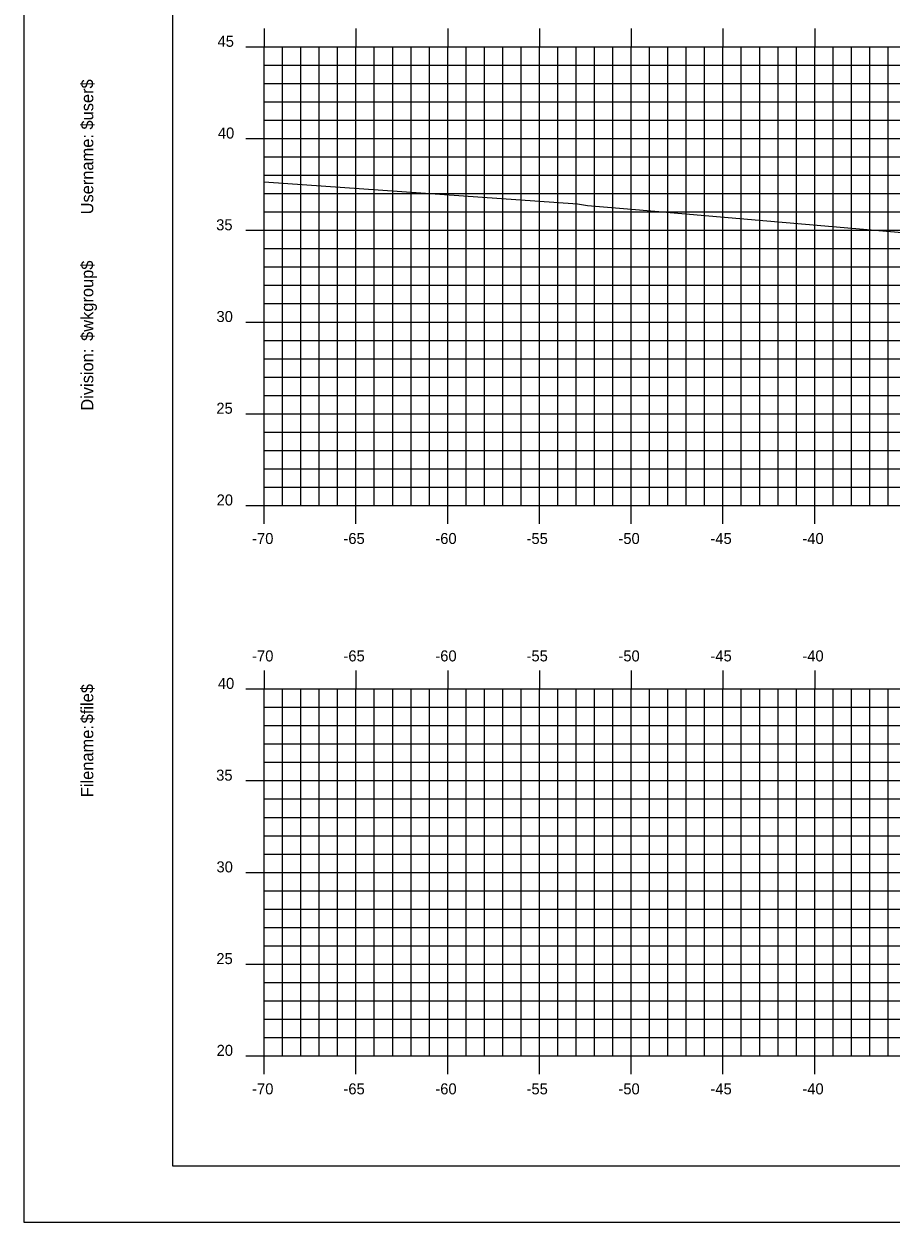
# Model space of a CAD drawing. Extents: x 1026131 to 1026301, y 394697 to 394807.
# Drawn here: x 1026131.3 to 1026178.5, y 394696.5 to 394761.9 of the extents above; entities that cross this region are included whole.
import ezdxf

# ---------------------------------------------------------------- set-up
doc = ezdxf.new("R2010")
doc.units = 0
for name, color, linetype in [('BORDER', 7, 'Continuous'), ('H_V ANNOTATION', 7, 'Continuous'), ('MAJOR', 7, 'Continuous'), ('MINOR', 7, 'Continuous'), ('PLOT BOUNDARY', 7, 'Continuous'), ('S_Roadway_Centerline', 7, 'Continuous')]:
    doc.layers.add(name, color=color, linetype=linetype)

msp = doc.modelspace()

# ---------------------------------------------------------------- linework, layer by layer
at = {"layer": 'BORDER'}
for p, q in [((1026139.345, 394804.607), (1026139.345, 394699.607)), ((1026139.345, 394699.607), (1026299.345, 394699.607))]:
    msp.add_line(p, q, dxfattribs=at)
at = {"layer": 'MAJOR'}
for p, q in [((1026144.344, 394761.609), (1026144.344, 394760.607)), ((1026149.344, 394761.609), (1026149.344, 394760.607)), ((1026154.344, 394761.609), (1026154.344, 394760.607)), ((1026159.344, 394761.609), (1026159.344, 394760.607)), ((1026164.344, 394761.609), (1026164.344, 394760.607)), ((1026169.344, 394761.609), (1026169.344, 394760.607)), ((1026174.344, 394761.609), (1026174.344, 394760.607)), ((1026143.342, 394760.607), (1026144.344, 394760.607)), ((1026144.344, 394760.607), (1026284.344, 394760.607)), ((1026144.344, 394735.607), (1026144.344, 394760.607)), ((1026149.344, 394735.607), (1026149.344, 394760.607)), ((1026154.344, 394735.607), (1026154.344, 394760.607)), ((1026159.344, 394735.607), (1026159.344, 394760.607)), ((1026164.344, 394735.607), (1026164.344, 394760.607)), ((1026169.344, 394735.607), (1026169.344, 394760.607)), ((1026174.344, 394735.607), (1026174.344, 394760.607)), ((1026143.342, 394755.607), (1026144.344, 394755.607)), ((1026144.344, 394755.607), (1026284.344, 394755.607)), ((1026143.342, 394750.607), (1026144.344, 394750.607)), ((1026144.344, 394750.607), (1026284.344, 394750.607)), ((1026143.342, 394745.607), (1026144.344, 394745.607)), ((1026144.344, 394745.607), (1026284.344, 394745.607)), ((1026143.342, 394740.607), (1026144.344, 394740.607)), ((1026144.344, 394740.607), (1026284.344, 394740.607)), ((1026143.342, 394735.607), (1026144.344, 394735.607)), ((1026144.344, 394735.607), (1026284.344, 394735.607)), ((1026144.344, 394734.605), (1026144.344, 394735.607)), ((1026149.344, 394734.605), (1026149.344, 394735.607)), ((1026154.344, 394734.605), (1026154.344, 394735.607)), ((1026159.344, 394734.605), (1026159.344, 394735.607)), ((1026164.344, 394734.605), (1026164.344, 394735.607)), ((1026169.344, 394734.605), (1026169.344, 394735.607)), ((1026174.344, 394734.605), (1026174.344, 394735.607)), ((1026144.344, 394726.609), (1026144.344, 394725.607)), ((1026149.344, 394726.609), (1026149.344, 394725.607)), ((1026154.344, 394726.609), (1026154.344, 394725.607)), ((1026159.344, 394726.609), (1026159.344, 394725.607)), ((1026164.344, 394726.609), (1026164.344, 394725.607)), ((1026169.344, 394726.609), (1026169.344, 394725.607)), ((1026174.344, 394726.609), (1026174.344, 394725.607)), ((1026143.342, 394725.607), (1026144.344, 394725.607)), ((1026144.344, 394725.607), (1026284.344, 394725.607)), ((1026144.344, 394705.607), (1026144.344, 394725.607)), ((1026149.344, 394705.607), (1026149.344, 394725.607)), ((1026154.344, 394705.607), (1026154.344, 394725.607)), ((1026159.344, 394705.607), (1026159.344, 394725.607)), ((1026164.344, 394705.607), (1026164.344, 394725.607)), ((1026169.344, 394705.607), (1026169.344, 394725.607)), ((1026174.344, 394705.607), (1026174.344, 394725.607)), ((1026143.342, 394720.607), (1026144.344, 394720.607)), ((1026144.344, 394720.607), (1026284.344, 394720.607)), ((1026143.342, 394715.607), (1026144.344, 394715.607)), ((1026144.344, 394715.607), (1026284.344, 394715.607)), ((1026143.342, 394710.607), (1026144.344, 394710.607)), ((1026144.344, 394710.607), (1026284.344, 394710.607)), ((1026143.342, 394705.607), (1026144.344, 394705.607)), ((1026144.344, 394705.607), (1026284.344, 394705.607)), ((1026144.344, 394704.605), (1026144.344, 394705.607)), ((1026149.344, 394704.605), (1026149.344, 394705.607)), ((1026154.344, 394704.605), (1026154.344, 394705.607)), ((1026159.344, 394704.605), (1026159.344, 394705.607)), ((1026164.344, 394704.605), (1026164.344, 394705.607)), ((1026169.344, 394704.605), (1026169.344, 394705.607)), ((1026174.344, 394704.605), (1026174.344, 394705.607))]:
    msp.add_line(p, q, dxfattribs=at)
at = {"layer": 'MINOR'}
for p, q in [((1026145.344, 394735.607), (1026145.344, 394760.607)), ((1026146.344, 394735.607), (1026146.344, 394760.607)), ((1026147.344, 394735.607), (1026147.344, 394760.607)), ((1026148.344, 394735.607), (1026148.344, 394760.607)), ((1026150.344, 394735.607), (1026150.344, 394760.607)), ((1026151.344, 394735.607), (1026151.344, 394760.607)), ((1026152.344, 394735.607), (1026152.344, 394760.607)), ((1026153.344, 394735.607), (1026153.344, 394760.607)), ((1026155.344, 394735.607), (1026155.344, 394760.607)), ((1026156.344, 394735.607), (1026156.344, 394760.607)), ((1026157.344, 394735.607), (1026157.344, 394760.607)), ((1026158.344, 394735.607), (1026158.344, 394760.607)), ((1026160.344, 394735.607), (1026160.344, 394760.607)), ((1026161.344, 394735.607), (1026161.344, 394760.607)), ((1026162.344, 394735.607), (1026162.344, 394760.607)), ((1026163.344, 394735.607), (1026163.344, 394760.607)), ((1026165.344, 394735.607), (1026165.344, 394760.607)), ((1026166.344, 394735.607), (1026166.344, 394760.607)), ((1026167.344, 394735.607), (1026167.344, 394760.607)), ((1026168.344, 394735.607), (1026168.344, 394760.607)), ((1026170.344, 394735.607), (1026170.344, 394760.607)), ((1026171.344, 394735.607), (1026171.344, 394760.607)), ((1026172.344, 394735.607), (1026172.344, 394760.607)), ((1026173.344, 394735.607), (1026173.344, 394760.607)), ((1026175.344, 394735.607), (1026175.344, 394760.607)), ((1026176.344, 394735.607), (1026176.344, 394760.607)), ((1026177.344, 394735.607), (1026177.344, 394760.607)), ((1026178.344, 394735.607), (1026178.344, 394760.607)), ((1026144.344, 394759.607), (1026284.344, 394759.607)), ((1026144.344, 394759.607), (1026145.346, 394759.607)), ((1026144.344, 394758.607), (1026284.344, 394758.607)), ((1026144.344, 394758.607), (1026145.346, 394758.607)), ((1026144.344, 394757.607), (1026284.344, 394757.607)), ((1026144.344, 394757.607), (1026145.346, 394757.607)), ((1026144.344, 394756.607), (1026284.344, 394756.607)), ((1026144.344, 394756.607), (1026145.346, 394756.607)), ((1026144.344, 394754.607), (1026284.344, 394754.607)), ((1026144.344, 394754.607), (1026145.346, 394754.607)), ((1026144.344, 394753.607), (1026284.344, 394753.607)), ((1026144.344, 394753.607), (1026145.346, 394753.607)), ((1026144.344, 394752.607), (1026284.344, 394752.607)), ((1026144.344, 394752.607), (1026145.346, 394752.607)), ((1026144.344, 394751.607), (1026284.344, 394751.607)), ((1026144.344, 394751.607), (1026145.346, 394751.607)), ((1026144.344, 394749.607), (1026284.344, 394749.607)), ((1026144.344, 394749.607), (1026145.346, 394749.607)), ((1026144.344, 394748.607), (1026284.344, 394748.607)), ((1026144.344, 394748.607), (1026145.346, 394748.607)), ((1026144.344, 394747.607), (1026284.344, 394747.607)), ((1026144.344, 394747.607), (1026145.346, 394747.607)), ((1026144.344, 394746.607), (1026284.344, 394746.607)), ((1026144.344, 394746.607), (1026145.346, 394746.607)), ((1026144.344, 394744.607), (1026284.344, 394744.607)), ((1026144.344, 394744.607), (1026145.346, 394744.607)), ((1026144.344, 394743.607), (1026284.344, 394743.607)), ((1026144.344, 394743.607), (1026145.346, 394743.607)), ((1026144.344, 394742.607), (1026284.344, 394742.607)), ((1026144.344, 394742.607), (1026145.346, 394742.607)), ((1026144.344, 394741.607), (1026284.344, 394741.607)), ((1026144.344, 394741.607), (1026145.346, 394741.607)), ((1026144.344, 394739.607), (1026284.344, 394739.607)), ((1026144.344, 394739.607), (1026145.346, 394739.607)), ((1026144.344, 394738.607), (1026284.344, 394738.607)), ((1026144.344, 394738.607), (1026145.346, 394738.607)), ((1026144.344, 394737.607), (1026284.344, 394737.607)), ((1026144.344, 394737.607), (1026145.346, 394737.607)), ((1026144.344, 394736.607), (1026284.344, 394736.607)), ((1026144.344, 394736.607), (1026145.346, 394736.607)), ((1026145.344, 394705.607), (1026145.344, 394725.607)), ((1026146.344, 394705.607), (1026146.344, 394725.607)), ((1026147.344, 394705.607), (1026147.344, 394725.607)), ((1026148.344, 394705.607), (1026148.344, 394725.607)), ((1026150.344, 394705.607), (1026150.344, 394725.607)), ((1026151.344, 394705.607), (1026151.344, 394725.607)), ((1026152.344, 394705.607), (1026152.344, 394725.607)), ((1026153.344, 394705.607), (1026153.344, 394725.607)), ((1026155.344, 394705.607), (1026155.344, 394725.607)), ((1026156.344, 394705.607), (1026156.344, 394725.607)), ((1026157.344, 394705.607), (1026157.344, 394725.607)), ((1026158.344, 394705.607), (1026158.344, 394725.607)), ((1026160.344, 394705.607), (1026160.344, 394725.607)), ((1026161.344, 394705.607), (1026161.344, 394725.607)), ((1026162.344, 394705.607), (1026162.344, 394725.607)), ((1026163.344, 394705.607), (1026163.344, 394725.607)), ((1026165.344, 394705.607), (1026165.344, 394725.607)), ((1026166.344, 394705.607), (1026166.344, 394725.607)), ((1026167.344, 394705.607), (1026167.344, 394725.607)), ((1026168.344, 394705.607), (1026168.344, 394725.607)), ((1026170.344, 394705.607), (1026170.344, 394725.607)), ((1026171.344, 394705.607), (1026171.344, 394725.607)), ((1026172.344, 394705.607), (1026172.344, 394725.607)), ((1026173.344, 394705.607), (1026173.344, 394725.607)), ((1026175.344, 394705.607), (1026175.344, 394725.607)), ((1026176.344, 394705.607), (1026176.344, 394725.607)), ((1026177.344, 394705.607), (1026177.344, 394725.607)), ((1026178.344, 394705.607), (1026178.344, 394725.607)), ((1026144.344, 394724.607), (1026284.344, 394724.607)), ((1026144.344, 394724.607), (1026145.346, 394724.607)), ((1026144.344, 394723.607), (1026284.344, 394723.607)), ((1026144.344, 394723.607), (1026145.346, 394723.607)), ((1026144.344, 394722.607), (1026284.344, 394722.607)), ((1026144.344, 394722.607), (1026145.346, 394722.607)), ((1026144.344, 394721.607), (1026284.344, 394721.607)), ((1026144.344, 394721.607), (1026145.346, 394721.607)), ((1026144.344, 394719.607), (1026284.344, 394719.607)), ((1026144.344, 394719.607), (1026145.346, 394719.607)), ((1026144.344, 394718.607), (1026284.344, 394718.607)), ((1026144.344, 394718.607), (1026145.346, 394718.607)), ((1026144.344, 394717.607), (1026284.344, 394717.607)), ((1026144.344, 394717.607), (1026145.346, 394717.607)), ((1026144.344, 394716.607), (1026284.344, 394716.607)), ((1026144.344, 394716.607), (1026145.346, 394716.607)), ((1026144.344, 394714.607), (1026284.344, 394714.607)), ((1026144.344, 394714.607), (1026145.346, 394714.607)), ((1026144.344, 394713.607), (1026284.344, 394713.607)), ((1026144.344, 394713.607), (1026145.346, 394713.607)), ((1026144.344, 394712.607), (1026284.344, 394712.607)), ((1026144.344, 394712.607), (1026145.346, 394712.607)), ((1026144.344, 394711.607), (1026284.344, 394711.607)), ((1026144.344, 394711.607), (1026145.346, 394711.607)), ((1026144.344, 394709.607), (1026284.344, 394709.607)), ((1026144.344, 394709.607), (1026145.346, 394709.607)), ((1026144.344, 394708.607), (1026284.344, 394708.607)), ((1026144.344, 394708.607), (1026145.346, 394708.607)), ((1026144.344, 394707.607), (1026284.344, 394707.607)), ((1026144.344, 394707.607), (1026145.346, 394707.607)), ((1026144.344, 394706.607), (1026284.344, 394706.607)), ((1026144.344, 394706.607), (1026145.346, 394706.607))]:
    msp.add_line(p, q, dxfattribs=at)
at = {"layer": 'PLOT BOUNDARY'}
msp.add_lwpolyline([(1026131.251, 394696.548), (1026301.251, 394696.548), (1026301.251, 394806.548), (1026131.251, 394806.548)], close=True, dxfattribs=at)
at = {"layer": 'S_Roadway_Centerline'}
msp.add_lwpolyline([(1026144.344, 394753.246), (1026161.416, 394752.044), (1026161.957, 394751.958), (1026164.577, 394751.744), (1026181.002, 394750.326)], dxfattribs=at)

# ---------------------------------------------------------------- texts
at = {"layer": 'BORDER'}
for s, p in [('$user$', (1026135.029, 394756.098)), ('Username:', (1026135.029, 394751.474)), ('$wkgroup$', (1026135.029, 394744.576)), ('Division:', (1026135.029, 394740.773)), ('$file$', (1026135.029, 394723.732)), ('Filename:', (1026135.029, 394719.705))]:
    msp.add_text(s, height=0.6696, rotation=90, dxfattribs=at).set_placement(p)
at = {"layer": 'H_V ANNOTATION'}
for s, p in [('45', (1026141.801, 394760.607)), ('40', (1026141.817, 394755.607)), ('35', (1026141.726, 394750.607)), ('30', (1026141.742, 394745.607)), ('25', (1026141.736, 394740.607)), ('20', (1026141.752, 394735.607)), ('-70', (1026143.686, 394733.507)), ('-65', (1026148.662, 394733.507)), ('-60', (1026153.67, 394733.507)), ('-55', (1026158.64, 394733.507)), ('-50', (1026163.648, 394733.507)), ('-45', (1026168.662, 394733.507)), ('-40', (1026173.67, 394733.507)), ('-70', (1026143.686, 394727.107)), ('-65', (1026148.662, 394727.107)), ('-60', (1026153.67, 394727.107)), ('-55', (1026158.64, 394727.107)), ('-50', (1026163.648, 394727.107)), ('-45', (1026168.662, 394727.107)), ('-40', (1026173.67, 394727.107)), ('40', (1026141.817, 394725.607)), ('35', (1026141.726, 394720.607)), ('30', (1026141.742, 394715.607)), ('25', (1026141.736, 394710.607)), ('20', (1026141.752, 394705.607)), ('-70', (1026143.686, 394703.507)), ('-65', (1026148.662, 394703.507)), ('-60', (1026153.67, 394703.507)), ('-55', (1026158.64, 394703.507)), ('-50', (1026163.648, 394703.507)), ('-45', (1026168.662, 394703.507)), ('-40', (1026173.67, 394703.507))]:
    msp.add_text(s, height=0.6, dxfattribs=at).set_placement(p)

doc.saveas('drawing.dxf')
